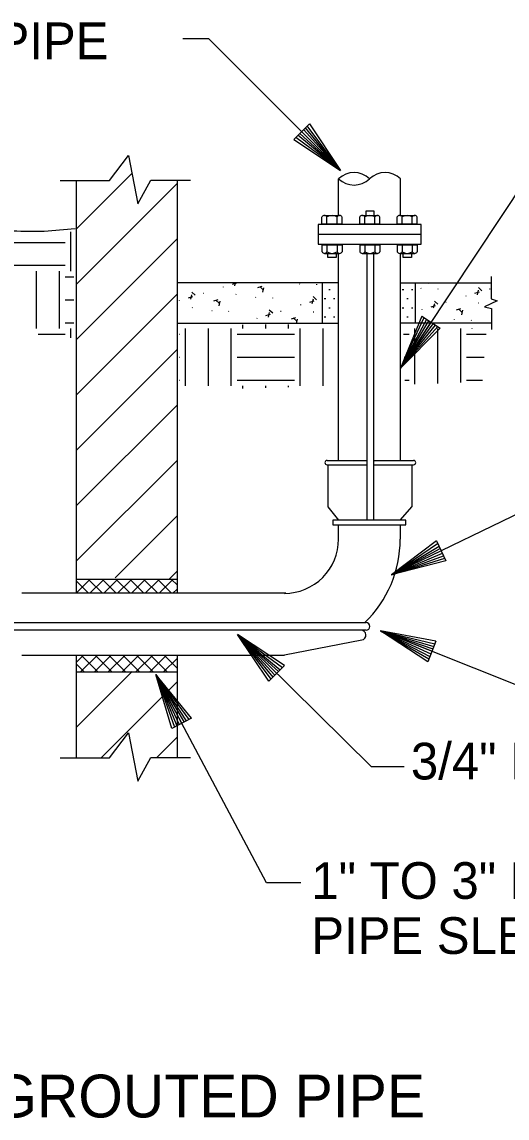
# Model space of a CAD drawing. Extents: x 10040.55 to 10045.84, y 10033.26 to 10035.76.
# Drawn here: x 10041.8924 to 10042.0246, y 10035.3007 to 10035.5994 of the extents above; entities that cross this region are included whole.
import ezdxf

# ---------------------------------------------------------------- set-up
doc = ezdxf.new("R2010")
doc.units = 0
doc.layers.add('Level 2', color=7, linetype='Continuous')

msp = doc.modelspace()

# ---------------------------------------------------------------- linework, layer by layer
at = {"layer": 'Level 2'}
for p, q in [((10041.966510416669, 10035.567406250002), (10041.970781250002, 10035.571666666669)), ((10041.979281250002, 10035.558885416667), (10041.968125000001, 10035.569020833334)), ((10041.968614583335, 10035.569520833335), (10041.979281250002, 10035.558885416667)), ((10041.979281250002, 10035.558885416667), (10041.969156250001, 10035.570052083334)), ((10041.979281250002, 10035.558885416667), (10041.969677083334, 10035.570583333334)), ((10041.979281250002, 10035.558885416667), (10041.970197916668, 10035.57109375)), ((10041.970781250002, 10035.571666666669), (10041.979281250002, 10035.558885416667)), ((10041.966510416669, 10035.567406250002), (10041.979281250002, 10035.558885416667)), ((10041.979281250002, 10035.558885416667), (10041.967052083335, 10035.567947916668)), ((10041.979281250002, 10035.558885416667), (10041.967635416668, 10035.5685625)), ((10041.907281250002, 10035.543010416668), (10041.922416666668, 10035.558145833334)), ((10041.907281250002, 10035.443708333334), (10041.907281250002, 10035.556218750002)), ((10041.907291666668, 10035.527927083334), (10041.93471875, 10035.555364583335)), ((10041.93471875, 10035.556218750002), (10041.93471875, 10035.443708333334)), ((10041.97871875, 10035.546687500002), (10041.97871875, 10035.556677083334)), ((10041.995520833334, 10035.556677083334), (10041.995520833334, 10035.546687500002)), ((10041.974197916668, 10035.544354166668), (10041.974197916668, 10035.546260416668)), ((10041.974885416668, 10035.546687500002), (10041.978989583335, 10035.546687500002)), ((10041.975562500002, 10035.544354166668), (10041.975562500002, 10035.546260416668)), ((10041.978312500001, 10035.544354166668), (10041.978312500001, 10035.546260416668)), ((10041.979677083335, 10035.544354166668), (10041.979677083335, 10035.546250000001)), ((10041.984510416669, 10035.544354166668), (10041.984510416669, 10035.546260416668)), ((10041.985197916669, 10035.546687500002), (10041.989302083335, 10035.546687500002)), ((10041.985875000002, 10035.544354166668), (10041.985875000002, 10035.546260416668)), ((10041.988625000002, 10035.544354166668), (10041.988625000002, 10035.546260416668)), ((10041.989989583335, 10035.544354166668), (10041.989989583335, 10035.546250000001)), ((10041.994697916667, 10035.544354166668), (10041.994697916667, 10035.546260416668)), ((10041.995385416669, 10035.546687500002), (10041.999489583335, 10035.546687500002)), ((10041.996062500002, 10035.544354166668), (10041.996062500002, 10035.546260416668)), ((10041.998812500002, 10035.544354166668), (10041.998812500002, 10035.546260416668)), ((10042.000177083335, 10035.544354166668), (10042.000177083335, 10035.546250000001)), ((10041.905739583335, 10035.531520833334), (10041.905739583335, 10035.542177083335)), ((10041.974197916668, 10035.544354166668), (10041.979677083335, 10035.544354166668)), ((10041.984510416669, 10035.544354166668), (10041.989989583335, 10035.544354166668)), ((10041.994697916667, 10035.544354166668), (10042.000177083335, 10035.544354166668)), ((10041.888552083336, 10035.539333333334), (10041.904177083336, 10035.539333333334)), ((10041.907291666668, 10035.51284375), (10041.93471875, 10035.540281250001)), ((10042.001229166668, 10035.541510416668), (10041.973187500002, 10035.541510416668)), ((10041.974197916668, 10035.538666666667), (10041.979677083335, 10035.538666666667)), ((10041.974197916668, 10035.538666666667), (10041.974197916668, 10035.536760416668)), ((10041.974885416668, 10035.536333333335), (10041.978989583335, 10035.536333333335)), ((10041.975562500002, 10035.538666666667), (10041.975562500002, 10035.536760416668)), ((10041.978312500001, 10035.538666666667), (10041.978312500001, 10035.536760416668)), ((10041.97871875, 10035.479937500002), (10041.97871875, 10035.536395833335)), ((10041.979677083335, 10035.538666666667), (10041.979677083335, 10035.536770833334)), ((10041.984510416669, 10035.538666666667), (10041.989989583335, 10035.538666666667)), ((10041.984510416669, 10035.538666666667), (10041.984510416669, 10035.536760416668)), ((10041.985197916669, 10035.536333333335), (10041.989302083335, 10035.536333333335)), ((10041.985875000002, 10035.538666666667), (10041.985875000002, 10035.536760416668)), ((10041.986385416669, 10035.536333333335), (10041.986385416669, 10035.463687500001)), ((10041.988354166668, 10035.463687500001), (10041.988354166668, 10035.536333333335)), ((10041.988625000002, 10035.538666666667), (10041.988625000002, 10035.536760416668)), ((10041.989989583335, 10035.538666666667), (10041.989989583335, 10035.536770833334)), ((10041.994697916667, 10035.538666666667), (10042.000177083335, 10035.538666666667)), ((10041.994697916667, 10035.538666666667), (10041.994697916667, 10035.536760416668)), ((10041.995385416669, 10035.536333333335), (10041.999489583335, 10035.536333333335)), ((10041.995520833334, 10035.536333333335), (10041.995520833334, 10035.479937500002)), ((10041.996062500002, 10035.538666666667), (10041.996062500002, 10035.536760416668)), ((10041.998812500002, 10035.538666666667), (10041.998812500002, 10035.536760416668)), ((10042.000177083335, 10035.538666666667), (10042.000177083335, 10035.536770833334)), ((10041.888552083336, 10035.533083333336), (10041.904177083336, 10035.533083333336)), ((10041.896364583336, 10035.515895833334), (10041.896364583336, 10035.531520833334)), ((10041.902614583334, 10035.515895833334), (10041.902614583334, 10035.531520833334)), ((10041.904177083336, 10035.529958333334), (10041.906552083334, 10035.529958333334)), ((10041.97871875, 10035.528322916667), (10041.93471875, 10035.528322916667)), ((10041.9473125, 10035.527145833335), (10041.947333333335, 10035.527250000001)), ((10041.949791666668, 10035.527916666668), (10041.950989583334, 10035.52828125)), ((10041.950552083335, 10035.528322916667), (10041.950364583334, 10035.527510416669)), ((10041.9578125, 10035.527343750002), (10041.956614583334, 10035.526979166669)), ((10041.957250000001, 10035.527270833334), (10041.95815625, 10035.526427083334)), ((10041.968145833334, 10035.52796875), (10041.968072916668, 10035.528041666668)), ((10041.972687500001, 10035.527916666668), (10041.972666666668, 10035.5278125)), ((10041.97428125, 10035.528291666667), (10041.97428125, 10035.517354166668)), ((10041.995520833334, 10035.528322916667), (10042.020250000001, 10035.528322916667)), ((10041.999635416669, 10035.528322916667), (10041.999635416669, 10035.517354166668)), ((10042.003135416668, 10035.52815625), (10042.0031875, 10035.528375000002)), ((10042.017739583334, 10035.526166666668), (10042.016822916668, 10035.527020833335)), ((10041.907291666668, 10035.497770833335), (10041.93471875, 10035.525197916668)), ((10041.937843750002, 10035.524260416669), (10041.939031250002, 10035.524625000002)), ((10041.938677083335, 10035.525072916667), (10041.938395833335, 10035.523864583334)), ((10041.93965625, 10035.524916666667), (10041.938750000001, 10035.525760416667)), ((10041.941822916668, 10035.525479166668), (10041.941947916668, 10035.525510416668)), ((10041.950833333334, 10035.525208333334), (10041.950739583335, 10035.525177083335)), ((10041.956187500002, 10035.524312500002), (10041.956114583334, 10035.524385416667)), ((10041.958104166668, 10035.525729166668), (10041.958385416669, 10035.526947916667)), ((10041.960729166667, 10035.524260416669), (10041.960708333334, 10035.524166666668)), ((10041.972718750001, 10035.523708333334), (10041.971802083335, 10035.5245625)), ((10041.974802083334, 10035.524020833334), (10041.975218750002, 10035.524020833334)), ((10041.976052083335, 10035.526520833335), (10041.976468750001, 10035.526520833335)), ((10041.977302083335, 10035.524020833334), (10041.977718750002, 10035.524020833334)), ((10041.978552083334, 10035.526520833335), (10041.978572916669, 10035.526520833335)), ((10041.996062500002, 10035.526520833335), (10041.996468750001, 10035.526520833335)), ((10041.997302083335, 10035.524020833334), (10041.99771875, 10035.524020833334)), ((10041.998552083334, 10035.526520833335), (10041.998979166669, 10035.526520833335)), ((10042.001208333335, 10035.526770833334), (10042.001135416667, 10035.526833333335)), ((10042.005760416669, 10035.526697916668), (10042.005739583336, 10035.52659375)), ((10042.013458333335, 10035.524708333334), (10042.013479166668, 10035.524802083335)), ((10042.015895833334, 10035.525468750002), (10042.01709375, 10035.525833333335)), ((10042.016791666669, 10035.526291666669), (10042.016510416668, 10035.525072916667)), ((10042.019885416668, 10035.526687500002), (10042.02, 10035.526718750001)), ((10041.904177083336, 10035.523708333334), (10041.906552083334, 10035.523708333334)), ((10041.935354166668, 10035.523500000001), (10041.935375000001, 10035.523593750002)), ((10041.938885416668, 10035.521552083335), (10041.93878125, 10035.521520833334)), ((10041.945854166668, 10035.523687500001), (10041.944656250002, 10035.523322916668)), ((10041.945291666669, 10035.523614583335), (10041.946197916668, 10035.522760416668)), ((10041.946145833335, 10035.522072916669), (10041.946427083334, 10035.523291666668)), ((10041.968427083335, 10035.522270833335), (10041.968447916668, 10035.522375)), ((10041.970895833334, 10035.52303125), (10041.972083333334, 10035.523395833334)), ((10041.97175, 10035.523854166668), (10041.971468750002, 10035.522635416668)), ((10041.976052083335, 10035.521520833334), (10041.976468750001, 10035.521520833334)), ((10041.978552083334, 10035.521520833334), (10041.978583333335, 10035.521520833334)), ((10041.996062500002, 10035.521520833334), (10041.996468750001, 10035.521520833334)), ((10041.998552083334, 10035.521520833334), (10041.998979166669, 10035.521520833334)), ((10042.001500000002, 10035.521052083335), (10042.001520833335, 10035.52115625)), ((10042.003947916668, 10035.521812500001), (10042.005135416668, 10035.522177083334)), ((10042.004822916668, 10035.522635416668), (10042.004541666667, 10035.521416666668)), ((10042.005781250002, 10035.522500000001), (10042.004864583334, 10035.523354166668)), ((10042.007927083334, 10035.52303125), (10042.008052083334, 10035.523062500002)), ((10042.011958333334, 10035.521239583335), (10042.010760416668, 10035.520875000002)), ((10042.011406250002, 10035.521208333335), (10042.012322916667, 10035.520354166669)), ((10042.0169375, 10035.522760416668), (10042.016843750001, 10035.522729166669)), ((10041.944229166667, 10035.520645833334), (10041.944156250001, 10035.520718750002)), ((10041.948770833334, 10035.520614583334), (10041.948750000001, 10035.520510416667)), ((10041.956458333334, 10035.518625), (10041.956489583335, 10035.518718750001)), ((10041.958937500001, 10035.519375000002), (10041.960135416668, 10035.519750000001)), ((10041.959791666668, 10035.520208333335), (10041.959510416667, 10035.518989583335)), ((10041.960760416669, 10035.520052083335), (10041.95984375, 10035.520895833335)), ((10041.962916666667, 10035.520593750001), (10041.963041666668, 10035.520635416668)), ((10041.966958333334, 10035.5188125), (10041.965760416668, 10035.518447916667)), ((10041.966385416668, 10035.518750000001), (10041.967302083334, 10035.517895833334)), ((10041.967270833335, 10035.517270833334), (10041.967531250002, 10035.518416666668)), ((10041.9719375, 10035.520333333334), (10041.971833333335, 10035.520302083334)), ((10041.974802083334, 10035.519020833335), (10041.975218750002, 10035.519020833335)), ((10041.977302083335, 10035.519020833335), (10041.977718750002, 10035.519020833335)), ((10042.001406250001, 10035.519260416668), (10041.995583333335, 10035.505052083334)), ((10041.995583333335, 10035.505052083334), (10042.002041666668, 10035.518833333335)), ((10041.995583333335, 10035.505052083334), (10042.002760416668, 10035.518385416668)), ((10041.997302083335, 10035.519020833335), (10041.99771875, 10035.519020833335)), ((10042.001406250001, 10035.519260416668), (10042.006416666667, 10035.515916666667)), ((10042.004989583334, 10035.519114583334), (10042.004885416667, 10035.519083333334)), ((10042.010354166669, 10035.518239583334), (10042.01028125, 10035.518312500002)), ((10042.012291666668, 10035.519635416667), (10042.012572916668, 10035.52084375)), ((10042.014916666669, 10035.518166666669), (10042.014895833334, 10035.518062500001)), ((10041.904177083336, 10035.517458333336), (10041.906552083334, 10035.517458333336)), ((10041.905739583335, 10035.51334375), (10041.905739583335, 10035.515895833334)), ((10041.93471875, 10035.517343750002), (10041.97871875, 10035.517343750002)), ((10041.936989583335, 10035.500270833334), (10041.936989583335, 10035.515895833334)), ((10041.943239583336, 10035.500270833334), (10041.943239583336, 10035.515895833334)), ((10041.949489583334, 10035.500270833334), (10041.949489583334, 10035.515895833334)), ((10041.952614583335, 10035.515895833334), (10041.952614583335, 10035.516864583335)), ((10041.958864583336, 10035.515895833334), (10041.958864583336, 10035.516916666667)), ((10041.965114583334, 10035.515895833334), (10041.965114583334, 10035.516968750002)), ((10041.968239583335, 10035.500270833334), (10041.968239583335, 10035.515895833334)), ((10041.974489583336, 10035.500270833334), (10041.974489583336, 10035.515895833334)), ((10042.020250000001, 10035.517343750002), (10041.995520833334, 10035.517343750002)), ((10041.995583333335, 10035.505052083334), (10042.003302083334, 10035.518000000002)), ((10042.003895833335, 10035.517614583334), (10041.995583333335, 10035.505052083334)), ((10041.995583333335, 10035.505052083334), (10042.004520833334, 10035.517187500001)), ((10041.995583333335, 10035.505052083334), (10042.005145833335, 10035.516791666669)), ((10041.995583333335, 10035.505052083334), (10042.005739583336, 10035.516375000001)), ((10042.006416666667, 10035.515916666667), (10041.995583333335, 10035.505052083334)), ((10041.999489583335, 10035.500677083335), (10041.999489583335, 10035.515895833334)), ((10042.005739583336, 10035.500906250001), (10042.005739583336, 10035.515895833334)), ((10042.012, 10035.501135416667), (10042.012, 10035.515895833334)), ((10042.015114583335, 10035.515895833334), (10042.015114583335, 10035.516000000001)), ((10041.89684375, 10035.514333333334), (10041.904177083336, 10035.514333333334)), ((10041.935343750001, 10035.514333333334), (10041.935427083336, 10035.514333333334)), ((10041.951052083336, 10035.514333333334), (10041.966677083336, 10035.514333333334)), ((10041.996437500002, 10035.514333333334), (10041.997927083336, 10035.514333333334)), ((10042.013552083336, 10035.514333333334), (10042.018916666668, 10035.514333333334)), ((10041.907291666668, 10035.482687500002), (10041.93471875, 10035.510114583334)), ((10041.935343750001, 10035.508083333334), (10041.935427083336, 10035.508083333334)), ((10041.951052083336, 10035.508083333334), (10041.966677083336, 10035.508083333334)), ((10041.996593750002, 10035.508083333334), (10041.997927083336, 10035.508083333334)), ((10042.013552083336, 10035.508083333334), (10042.018427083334, 10035.508083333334)), ((10041.935343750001, 10035.501833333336), (10041.935427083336, 10035.501833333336)), ((10041.951052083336, 10035.501833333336), (10041.966677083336, 10035.501833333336)), ((10041.952614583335, 10035.499510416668), (10041.952614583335, 10035.500270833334)), ((10041.958864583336, 10035.499677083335), (10041.958864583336, 10035.500270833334)), ((10041.965114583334, 10035.499843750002), (10041.965114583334, 10035.500270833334)), ((10041.996750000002, 10035.501833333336), (10041.997927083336, 10035.501833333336)), ((10042.013552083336, 10035.501833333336), (10042.017927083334, 10035.501833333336)), ((10041.907302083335, 10035.467604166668), (10041.93471875, 10035.495020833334)), ((10041.907302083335, 10035.452520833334), (10041.934729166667, 10035.479937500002)), ((10041.975583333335, 10035.479937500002), (10041.986385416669, 10035.479937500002)), ((10041.988354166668, 10035.479937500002), (10041.999177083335, 10035.479937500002)), ((10041.975583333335, 10035.478760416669), (10041.986385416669, 10035.478760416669)), ((10041.9758125, 10035.478760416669), (10041.9758125, 10035.467281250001)), ((10041.988354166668, 10035.478760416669), (10041.999177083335, 10035.478760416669)), ((10041.998812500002, 10035.467322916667), (10041.998812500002, 10035.478760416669)), ((10041.9758125, 10035.467281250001), (10041.97871875, 10035.463687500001)), ((10041.995541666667, 10035.463687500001), (10041.998812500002, 10035.467322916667)), ((10041.917843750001, 10035.44796875), (10041.934729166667, 10035.464854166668)), ((10041.97871875, 10035.458437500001), (10041.97871875, 10035.462354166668)), ((10041.995520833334, 10035.462354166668), (10041.995520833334, 10035.458437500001)), ((10042.005375, 10035.457989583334), (10041.993114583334, 10035.448750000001)), ((10041.993114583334, 10035.448750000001), (10042.005708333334, 10035.457302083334)), ((10041.993114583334, 10035.448750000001), (10042.006093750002, 10035.456552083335)), ((10041.993114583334, 10035.448750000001), (10042.006364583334, 10035.4559375)), ((10042.005375, 10035.457989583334), (10042.007979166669, 10035.4525625)), ((10042.006677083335, 10035.455312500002), (10041.993114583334, 10035.448750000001)), ((10041.993114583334, 10035.448750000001), (10042.007000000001, 10035.454625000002)), ((10041.993114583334, 10035.448750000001), (10042.007333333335, 10035.453958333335)), ((10041.993114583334, 10035.448750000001), (10042.007635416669, 10035.453302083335)), ((10042.007979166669, 10035.4525625), (10041.993114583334, 10035.448750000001)), ((10041.932635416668, 10035.447677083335), (10041.934729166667, 10035.449770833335)), ((10041.907281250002, 10035.443812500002), (10041.910958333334, 10035.447479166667)), ((10041.910604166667, 10035.443708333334), (10041.907291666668, 10035.447010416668)), ((10041.93471875, 10035.447479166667), (10041.907302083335, 10035.447479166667)), ((10041.914375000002, 10035.443708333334), (10041.91059375, 10035.447479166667)), ((10041.910947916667, 10035.443708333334), (10041.914729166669, 10035.447479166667)), ((10041.918145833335, 10035.443708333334), (10041.914364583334, 10035.447479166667)), ((10041.914718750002, 10035.443708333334), (10041.918500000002, 10035.447479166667)), ((10041.921916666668, 10035.443708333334), (10041.918145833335, 10035.447479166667)), ((10041.918500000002, 10035.443708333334), (10041.922270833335, 10035.447479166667)), ((10041.925687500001, 10035.443708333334), (10041.921916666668, 10035.447479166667)), ((10041.922270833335, 10035.443708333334), (10041.926041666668, 10035.447479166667)), ((10041.929458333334, 10035.443708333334), (10041.925687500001, 10035.447479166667)), ((10041.926041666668, 10035.443708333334), (10041.9298125, 10035.447479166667)), ((10041.933229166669, 10035.443708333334), (10041.929458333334, 10035.447479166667)), ((10041.9298125, 10035.443708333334), (10041.933583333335, 10035.447479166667)), ((10041.93471875, 10035.445979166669), (10041.933229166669, 10035.447479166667)), ((10041.964333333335, 10035.443708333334), (10041.8924375, 10035.443708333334)), ((10041.933583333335, 10035.443708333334), (10041.93471875, 10035.444854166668)), ((10041.812458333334, 10035.435739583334), (10041.986208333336, 10035.435739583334)), ((10041.986208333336, 10035.433645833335), (10041.812562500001, 10035.433645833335)), ((10041.961875, 10035.421895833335), (10041.951135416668, 10035.432458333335)), ((10041.959718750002, 10035.419739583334), (10041.951135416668, 10035.432458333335)), ((10041.963958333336, 10035.424020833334), (10041.951135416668, 10035.432458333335)), ((10041.951135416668, 10035.432458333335), (10041.960822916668, 10035.420822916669)), ((10041.951135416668, 10035.432458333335), (10041.962843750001, 10035.422864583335)), ((10041.951135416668, 10035.432458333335), (10041.960302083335, 10035.420312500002)), ((10041.951135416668, 10035.432458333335), (10041.961333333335, 10035.421364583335)), ((10041.951135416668, 10035.432458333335), (10041.962364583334, 10035.422395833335)), ((10041.951135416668, 10035.432458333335), (10041.963427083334, 10035.423479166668)), ((10042.004156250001, 10035.42790625), (10041.990145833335, 10035.433447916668)), ((10042.003010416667, 10035.425083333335), (10041.990145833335, 10035.433447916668)), ((10042.005250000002, 10035.430677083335), (10041.990145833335, 10035.433447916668)), ((10041.990145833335, 10035.433447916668), (10042.003604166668, 10035.426510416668)), ((10041.990145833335, 10035.433447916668), (10042.004666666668, 10035.429177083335)), ((10041.990145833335, 10035.433447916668), (10042.003322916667, 10035.425843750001)), ((10041.990145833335, 10035.433447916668), (10042.003864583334, 10035.427208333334)), ((10041.990145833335, 10035.433447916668), (10042.004406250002, 10035.428562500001)), ((10041.990145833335, 10035.433447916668), (10042.004958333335, 10035.42996875)), ((10041.985020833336, 10035.430989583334), (10041.963989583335, 10035.426895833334)), ((10042.005250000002, 10035.430677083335), (10042.003010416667, 10035.425083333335)), ((10041.8924375, 10035.426895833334), (10041.963989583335, 10035.426895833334)), ((10041.907281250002, 10035.398885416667), (10041.907281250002, 10035.426781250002)), ((10041.907291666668, 10035.424958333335), (10041.909114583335, 10035.426781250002)), ((10041.90840625, 10035.422302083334), (10041.912885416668, 10035.426781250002)), ((10041.913145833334, 10035.422302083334), (10041.908666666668, 10035.426781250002)), ((10041.912177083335, 10035.422302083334), (10041.916656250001, 10035.426781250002)), ((10041.916916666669, 10035.422302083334), (10041.912437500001, 10035.426781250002)), ((10041.915947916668, 10035.422302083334), (10041.920427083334, 10035.426781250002)), ((10041.920687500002, 10035.422302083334), (10041.916208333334, 10035.426781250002)), ((10041.919718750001, 10035.422302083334), (10041.924197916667, 10035.426781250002)), ((10041.924458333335, 10035.422302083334), (10041.919979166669, 10035.426781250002)), ((10041.923489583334, 10035.422302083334), (10041.927968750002, 10035.426781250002)), ((10041.928229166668, 10035.422302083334), (10041.923750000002, 10035.426781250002)), ((10041.927260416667, 10035.422302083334), (10041.931739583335, 10035.426781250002)), ((10041.932, 10035.422302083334), (10041.927520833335, 10035.426781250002)), ((10041.931031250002, 10035.422302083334), (10041.93471875, 10035.425989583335)), ((10041.93471875, 10035.423354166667), (10041.931291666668, 10035.426781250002)), ((10041.93471875, 10035.426781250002), (10041.93471875, 10035.398885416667)), ((10041.909375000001, 10035.422302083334), (10041.907291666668, 10035.424385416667)), ((10041.963958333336, 10035.424020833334), (10041.959718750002, 10035.419739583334)), ((10041.907291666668, 10035.407250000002), (10041.922427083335, 10035.422395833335)), ((10041.907302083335, 10035.422302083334), (10041.93471875, 10035.422302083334)), ((10041.914114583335, 10035.398989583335), (10041.934729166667, 10035.419604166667)), ((10041.935979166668, 10035.408291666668), (10041.928906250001, 10035.421593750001)), ((10041.933281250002, 10035.406885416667), (10041.928906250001, 10035.421593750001)), ((10041.938614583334, 10035.409697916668), (10041.928906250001, 10035.421593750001)), ((10041.928906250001, 10035.421593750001), (10041.934656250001, 10035.407593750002)), ((10041.928906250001, 10035.421593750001), (10041.937197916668, 10035.408927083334)), ((10041.928906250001, 10035.421593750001), (10041.934010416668, 10035.407260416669)), ((10041.928906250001, 10035.421593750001), (10041.935312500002, 10035.407947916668)), ((10041.928906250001, 10035.421593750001), (10041.936604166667, 10035.408635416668)), ((10041.928906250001, 10035.421593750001), (10041.9379375, 10035.409343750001)), ((10041.938614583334, 10035.409697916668), (10041.933281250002, 10035.406885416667)), ((10041.929177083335, 10035.398968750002), (10041.93471875, 10035.404510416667))]:
    msp.add_line(p, q, dxfattribs=at)
for points in [[(10041.936312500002, 10035.594937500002), (10041.943229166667, 10035.594937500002), (10041.979281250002, 10035.558885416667)], [(10041.902843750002, 10035.556197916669), (10041.916322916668, 10035.556197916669), (10041.921500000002, 10035.56296875), (10041.924010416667, 10035.549802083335), (10041.927520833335, 10035.556270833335), (10041.938333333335, 10035.556270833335)], [(10042.037562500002, 10035.556416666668), (10042.02965625, 10035.556416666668), (10041.995583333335, 10035.505052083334)], [(10041.988385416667, 10035.546697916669), (10041.988385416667, 10035.54784375), (10041.986125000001, 10035.54784375), (10041.986125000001, 10035.546697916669)], [(10041.978072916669, 10035.536322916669), (10041.978072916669, 10035.535177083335), (10041.9758125, 10035.535177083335), (10041.9758125, 10035.536322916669)], [(10041.998572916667, 10035.536322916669), (10041.998572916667, 10035.535177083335), (10041.996312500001, 10035.535177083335), (10041.996312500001, 10035.536322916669)], [(10042.020281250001, 10035.530020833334), (10042.020281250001, 10035.523958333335), (10042.021979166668, 10035.523385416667), (10042.018500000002, 10035.521770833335), (10042.020364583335, 10035.521291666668), (10042.020364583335, 10035.515635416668)], [(10042.042000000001, 10035.468510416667), (10042.034104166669, 10035.468510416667), (10041.993114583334, 10035.448750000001)], [(10041.9965625, 10035.396406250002), (10041.987677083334, 10035.396406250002), (10041.951135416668, 10035.432458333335)], [(10042.037562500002, 10035.418135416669), (10042.028666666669, 10035.418135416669), (10041.990145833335, 10035.433447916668)], [(10041.968416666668, 10035.364791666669), (10041.95903125, 10035.364791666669), (10041.928906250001, 10035.421593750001)], [(10041.902843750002, 10035.398895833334), (10041.916322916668, 10035.398895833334), (10041.921500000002, 10035.405666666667), (10041.924010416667, 10035.392500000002), (10041.927520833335, 10035.398968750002), (10041.938333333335, 10035.398968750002)]]:
    msp.add_lwpolyline(points, dxfattribs=at)
for points in [[(10041.973145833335, 10035.544239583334), (10041.973145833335, 10035.538864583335), (10042.001229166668, 10035.538864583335), (10042.001229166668, 10035.544239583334)], [(10041.977145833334, 10035.463687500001), (10041.977145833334, 10035.462354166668), (10041.997020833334, 10035.462354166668), (10041.997020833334, 10035.463687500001)]]:
    msp.add_lwpolyline(points, close=True, dxfattribs=at)
for centre, radius, start, end in [((10041.98294002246, 10035.55230906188), 0.006074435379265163, 45.97749722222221, 134.02119166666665), ((10041.991382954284, 10035.55230906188), 0.006074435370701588, 45.97880833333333, 134.0225027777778), ((10041.98294002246, 10035.56104510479), 0.006074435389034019, 225.97880833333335, 314.0225027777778), ((10041.974880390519, 10035.545912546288), 0.0007663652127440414, 27.88770000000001, 152.03418611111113), ((10041.976935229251, 10035.544146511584), 0.0025319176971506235, 57.006158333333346, 122.94297500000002), ((10041.978990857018, 10035.545906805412), 0.000766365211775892, 26.78268611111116, 151.83909722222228), ((10041.98519289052, 10035.545912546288), 0.0007663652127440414, 27.88770000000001, 152.03418611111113), ((10041.98724772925, 10035.544146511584), 0.0025319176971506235, 57.006158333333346, 122.94297500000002), ((10041.989303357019, 10035.545906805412), 0.000766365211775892, 26.78268611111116, 151.83909722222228), ((10041.99538039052, 10035.545912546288), 0.0007663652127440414, 27.88770000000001, 152.03418611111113), ((10041.99743522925, 10035.544146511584), 0.0025319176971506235, 57.006158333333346, 122.94297500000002), ((10041.999490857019, 10035.545906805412), 0.000766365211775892, 26.78268611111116, 151.83909722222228), ((10041.974880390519, 10035.53710828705), 0.0007663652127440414, 207.9658138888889, 332.1123), ((10041.976935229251, 10035.538874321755), 0.0025319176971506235, 237.05702500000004, 302.9938416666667), ((10041.978990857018, 10035.537114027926), 0.0007663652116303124, 208.16090277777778, 333.2173138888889), ((10041.98519289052, 10035.53710828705), 0.0007663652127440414, 207.9658138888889, 332.1123), ((10041.98724772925, 10035.538874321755), 0.0025319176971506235, 237.05702500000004, 302.9938416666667), ((10041.989303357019, 10035.537114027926), 0.0007663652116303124, 208.16090277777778, 333.2173138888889), ((10041.99538039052, 10035.53710828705), 0.0007663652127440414, 207.9658138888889, 332.1123), ((10041.99743522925, 10035.538874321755), 0.0025319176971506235, 237.05702500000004, 302.9938416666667), ((10041.999490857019, 10035.537114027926), 0.0007663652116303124, 208.16090277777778, 333.2173138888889), ((10041.975583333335, 10035.479348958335), 0.0005885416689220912, 90, 270), ((10041.999177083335, 10035.479348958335), 0.0005885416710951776, 270, 90), ((10041.963985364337, 10035.45843629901), 0.014732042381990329, 269.9846972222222, 359.9999972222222), ((10041.963983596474, 10035.458436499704), 0.03153853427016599, 313.9738583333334, 0.0018166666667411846), ((10041.986208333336, 10035.434692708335), 0.0010468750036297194, 270, 90), ((10041.984841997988, 10035.43231281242), 0.0013330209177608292, 277.6969277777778, 91.68871944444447)]:
    msp.add_arc(centre, radius, start, end, dxfattribs=at)
msp.add_spline([(10041.906927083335, 10035.543031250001), (10041.898479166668, 10035.542343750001), (10041.881395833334, 10035.542854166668), (10041.868104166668, 10035.543031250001), (10041.85015625, 10035.542166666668), (10041.830833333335, 10035.541822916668), (10041.816854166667, 10035.542343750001)], degree=3, dxfattribs=at)

# ---------------------------------------------------------------- texts
for s, height, p in [('STEEL PIPE', 0.010000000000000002, (10041.8394375, 10035.589260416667)), ('3/4" ROD', 0.010000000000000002, (10041.998437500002, 10035.392989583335)), ('1" TO 3" MASTIC', 0.010000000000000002, (10041.971302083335, 10035.360447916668)), ('PIPE SLEEVE', 0.010000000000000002, (10041.971302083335, 10035.345447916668)), ('UNGROUTED PIPE', 0.011666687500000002, (10041.861864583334, 10035.300885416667))]:
    msp.add_text(s, height=height, dxfattribs=at).set_placement(p)

doc.saveas('drawing.dxf')
